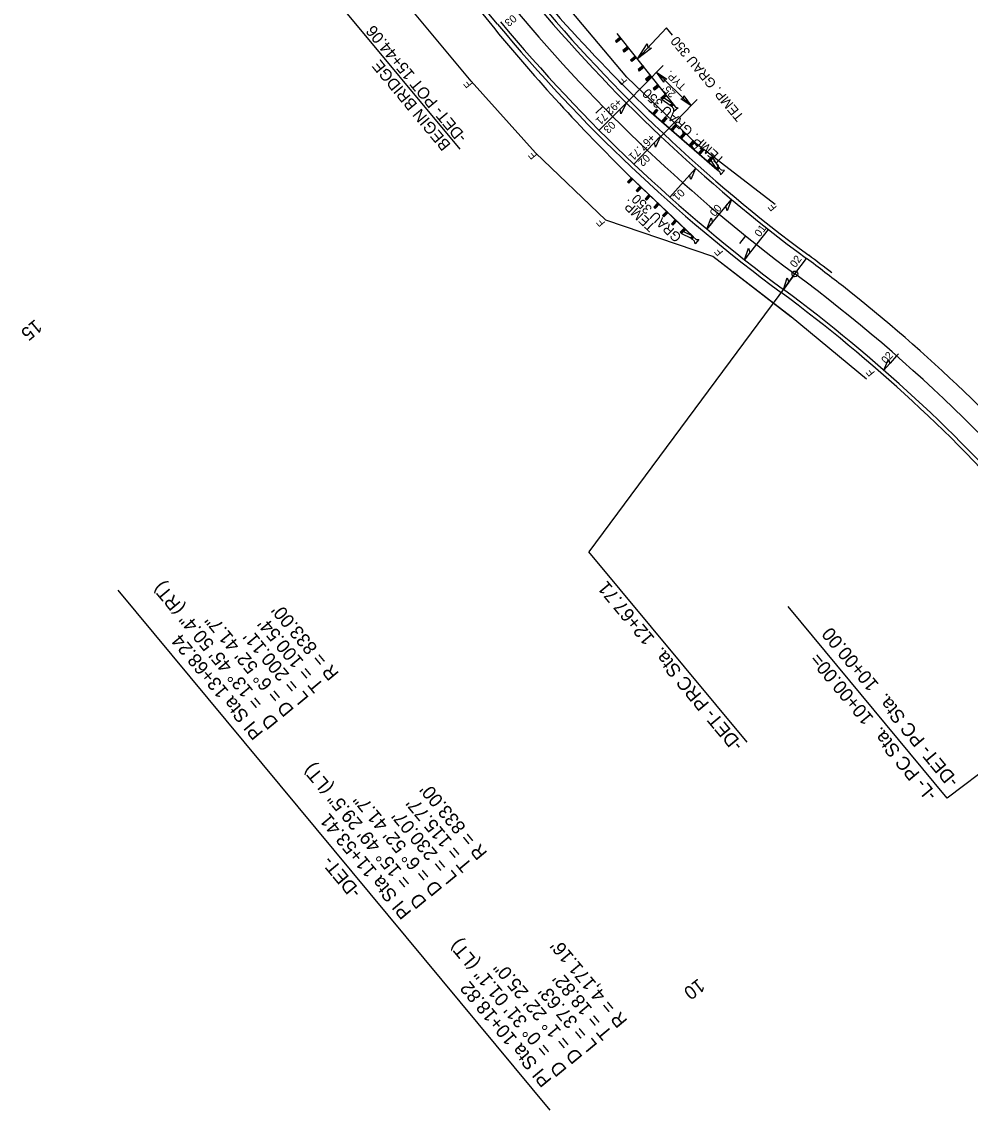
# Model space of a CAD drawing. Extents: x 2597390 to 2598563, y 852595 to 853909.
# Drawn here: x 2597806 to 2598297, y 852595 to 853159 of the extents above; entities that cross this region are included whole.
import ezdxf

# ---------------------------------------------------------------- set-up
doc = ezdxf.new("R2010")
doc.units = 0
for name, color, linetype in [('Prop DSN Text', 7, 'Continuous'), ('Prop EOT', 7, 'Continuous'), ('Prop Guardrail Anchor Unit CELL', 7, 'Continuous'), ('Prop Guardrail Temporary', 7, 'Continuous'), ('Prop Horizontal Alignment', 7, 'Continuous'), ('Prop Horizontal Alignment Curve and Spiral Data', 7, 'Continuous'), ('Prop Horizontal Alignment Station Label', 7, 'Continuous'), ('Prop Horizontal Alignment Tick Label', 7, 'Continuous'), ('Prop Horizontal Alignment Tick Small', 7, 'Continuous'), ('Prop Lane Lines', 7, 'Continuous'), ('Prop Paved Shoulder', 7, 'Continuous'), ('Prop SS Fill Line', 7, 'Continuous'), ('Prop SS Misc', 7, 'Continuous'), ('Prop Superelevation  Arrow CELL', 7, 'Continuous'), ('Prop Superelevation Label', 7, 'Continuous'), ('Prop Terminator CELL', 7, 'Continuous')]:
    doc.layers.add(name, color=color, linetype=linetype)

msp = doc.modelspace()

# ---------------------------------------------------------------- linework, layer by layer
at = {"layer": 'Prop DSN Text'}
msp.add_lwpolyline([(2598032.88, 853093.04), (2597970.16, 853168.56), (2598012.79, 853224.24)], dxfattribs=at)
at = {"layer": 'Prop EOT'}
for centre, radius, start, end in [((2598702.35, 853697.75), 823, 219.70669, 233.47068), ((2598702.35, 853697.75), 843, 219.70669, 233.47068), ((2597710.69, 852359.03), 843, 51.83177, 53.47068), ((2597710.69, 852359.03), 823, 41.12046, 53.47068)]:
    msp.add_arc(centre, radius, start, end, dxfattribs=at)
at = {"layer": 'Prop Guardrail Anchor Unit CELL'}
for p, q in [((2598115.79, 853151.04), (2598113.44, 853149.17)), ((2598115.24, 853149.33), (2598113.44, 853149.17)), ((2598113.44, 853149.17), (2598114.07, 853148.39)), ((2598116.41, 853150.26), (2598114.07, 853148.39)), ((2598114.07, 853148.39), (2598114.61, 853150.11)), ((2598114.2, 853153.03), (2598143.35, 853116.48)), ((2598114.61, 853150.11), (2598116.41, 853150.26)), ((2598114.61, 853150.11), (2598115.24, 853149.33)), ((2598115.24, 853149.33), (2598115.79, 853151.04)), ((2598116.41, 853150.26), (2598115.24, 853149.33)), ((2598115.79, 853151.04), (2598116.41, 853150.26)), ((2598119.72, 853146.12), (2598117.33, 853144.21)), ((2598119.15, 853144.38), (2598117.33, 853144.21)), ((2598117.33, 853144.21), (2598117.95, 853143.43)), ((2598120.34, 853145.33), (2598117.95, 853143.43)), ((2598117.95, 853143.43), (2598118.52, 853145.16)), ((2598118.52, 853145.16), (2598120.34, 853145.33)), ((2598118.52, 853145.16), (2598119.15, 853144.38)), ((2598119.72, 853146.12), (2598119.15, 853144.38)), ((2598123.64, 853141.19), (2598121.26, 853139.29)), ((2598123.08, 853139.46), (2598121.26, 853139.29)), ((2598121.26, 853139.29), (2598121.89, 853138.51)), ((2598124.27, 853140.41), (2598121.89, 853138.51)), ((2598121.89, 853138.51), (2598122.45, 853140.24)), ((2598122.45, 853140.24), (2598124.27, 853140.41)), ((2598122.45, 853140.24), (2598123.08, 853139.46)), ((2598123.64, 853141.19), (2598123.08, 853139.46)), ((2598127.57, 853136.26), (2598125.2, 853134.37)), ((2598127.01, 853134.53), (2598125.2, 853134.37)), ((2598125.2, 853134.37), (2598125.82, 853133.59)), ((2598128.2, 853135.48), (2598125.82, 853133.59)), ((2598125.82, 853133.59), (2598126.39, 853135.32)), ((2598126.39, 853135.32), (2598128.2, 853135.48)), ((2598126.39, 853135.32), (2598127.01, 853134.53)), ((2598127.57, 853136.26), (2598127.01, 853134.53)), ((2598127.57, 853136.26), (2598128.2, 853135.48)), ((2598131.5, 853131.34), (2598129.05, 853129.38)), ((2598130.9, 853129.58), (2598129.05, 853129.38)), ((2598129.05, 853129.38), (2598129.67, 853128.6)), ((2598132.13, 853130.55), (2598129.67, 853128.6)), ((2598129.67, 853128.6), (2598130.27, 853130.36)), ((2598130.27, 853130.36), (2598132.13, 853130.55)), ((2598130.27, 853130.36), (2598130.9, 853129.58)), ((2598131.5, 853131.34), (2598130.9, 853129.58)), ((2598135.43, 853126.41), (2598133.08, 853124.54)), ((2598135.43, 853126.41), (2598134.88, 853124.69)), ((2598134.88, 853124.69), (2598133.08, 853124.54)), ((2598133.08, 853124.54), (2598133.71, 853123.76)), ((2598136.05, 853125.63), (2598133.71, 853123.76)), ((2598133.71, 853123.76), (2598134.26, 853125.47)), ((2598134.26, 853125.47), (2598136.05, 853125.63)), ((2598134.26, 853125.47), (2598134.88, 853124.69)), ((2598139.36, 853121.48), (2598136.96, 853119.57)), ((2598139.98, 853120.7), (2598137.59, 853118.79)), ((2598137.59, 853118.79), (2598138.16, 853120.53)), ((2598138.16, 853120.53), (2598139.98, 853120.7)), ((2598138.16, 853120.53), (2598138.78, 853119.74)), ((2598139.36, 853121.48), (2598138.78, 853119.74)), ((2598138.78, 853119.74), (2598136.96, 853119.57)), ((2598136.96, 853119.57), (2598137.59, 853118.79)), ((2598137.59, 853118.79), (2598141.86, 853115.93)), ((2598138.78, 853119.74), (2598143.04, 853116.87)), ((2598143.04, 853116.87), (2598141.86, 853115.93)), ((2598143.66, 853116.09), (2598141.86, 853115.93)), ((2598141.86, 853115.93), (2598142.18, 853115.54)), ((2598141.86, 853115.93), (2598142.49, 853115.15)), ((2598142.37, 853115.63), (2598142.84, 853116.02)), ((2598143.67, 853114.05), (2598142.37, 853115.63)), ((2598142.49, 853115.15), (2598143.04, 853116.87)), ((2598143.66, 853116.09), (2598142.49, 853115.15)), ((2598142.84, 853116.02), (2598143.31, 853116.4)), ((2598143.31, 853116.4), (2598144.62, 853114.83)), ((2598130.77, 853113.24), (2598166.06, 853082.58)), ((2598132.69, 853111.57), (2598134.66, 853113.84)), ((2598134.43, 853112.05), (2598132.69, 853111.57)), ((2598132.69, 853111.57), (2598133.44, 853110.92)), ((2598133.44, 853110.92), (2598135.41, 853113.18)), ((2598133.67, 853112.7), (2598133.44, 853110.92)), ((2598133.44, 853110.92), (2598134.43, 853112.05)), ((2598135.41, 853113.18), (2598133.67, 853112.7)), ((2598133.67, 853112.7), (2598134.43, 853112.05)), ((2598134.43, 853112.05), (2598134.66, 853113.84)), ((2598134.66, 853113.84), (2598135.41, 853113.18)), ((2598137.45, 853107.44), (2598139.45, 853109.74)), ((2598139.2, 853107.94), (2598139.45, 853109.74)), ((2598139.45, 853109.74), (2598140.2, 853109.09)), ((2598143.76, 853112.6), (2598143.67, 853114.05)), ((2598146.03, 853114.47), (2598143.76, 853112.6)), ((2598144.62, 853114.83), (2598146.03, 853114.47)), ((2598137.45, 853107.44), (2598139.2, 853107.94)), ((2598138.2, 853106.78), (2598140.2, 853109.09)), ((2598138.45, 853108.59), (2598138.2, 853106.78)), ((2598140.2, 853109.09), (2598138.45, 853108.59)), ((2598138.45, 853108.59), (2598139.2, 853107.94)), ((2598142.2, 853103.31), (2598144.2, 853105.61)), ((2598142.2, 853103.31), (2598143.96, 853103.8)), ((2598142.96, 853102.65), (2598144.96, 853104.95)), ((2598143.2, 853104.46), (2598142.96, 853102.65)), ((2598144.96, 853104.95), (2598143.2, 853104.46)), ((2598143.2, 853104.46), (2598143.96, 853103.8)), ((2598143.96, 853103.8), (2598144.2, 853105.61)), ((2598144.2, 853105.61), (2598144.96, 853104.95)), ((2598146.96, 853099.17), (2598148.95, 853101.47)), ((2598146.96, 853099.17), (2598148.71, 853099.67)), ((2598146.96, 853099.17), (2598147.71, 853098.52)), ((2598147.71, 853098.52), (2598149.71, 853100.81)), ((2598147.96, 853100.32), (2598147.71, 853098.52)), ((2598149.71, 853100.81), (2598147.96, 853100.32)), ((2598147.96, 853100.32), (2598148.71, 853099.67)), ((2598148.71, 853099.67), (2598148.95, 853101.47)), ((2598148.95, 853101.47), (2598149.71, 853100.81)), ((2598151.72, 853095.04), (2598153.77, 853097.41)), ((2598151.72, 853095.04), (2598153.5, 853095.57)), ((2598152.47, 853094.39), (2598154.53, 853096.76)), ((2598152.74, 853096.23), (2598152.47, 853094.39)), ((2598154.53, 853096.76), (2598152.74, 853096.23)), ((2598152.74, 853096.23), (2598153.5, 853095.57)), ((2598153.5, 853095.57), (2598153.77, 853097.41)), ((2598153.77, 853097.41), (2598154.53, 853096.76)), ((2598156.47, 853090.91), (2598158.44, 853093.17)), ((2598157.23, 853090.25), (2598159.2, 853092.52)), ((2598159.2, 853092.52), (2598157.46, 853092.04)), ((2598158.21, 853091.39), (2598158.44, 853093.17)), ((2598158.44, 853093.17), (2598159.2, 853092.52)), ((2598156.47, 853090.91), (2598158.21, 853091.39)), ((2598157.46, 853092.04), (2598157.23, 853090.25)), ((2598157.46, 853092.04), (2598158.21, 853091.39)), ((2598161.23, 853086.78), (2598163.24, 853089.09)), ((2598161.23, 853086.78), (2598162.99, 853087.28)), ((2598161.99, 853086.12), (2598164, 853088.43)), ((2598162.24, 853087.93), (2598161.99, 853086.12)), ((2598164, 853088.43), (2598162.24, 853087.93)), ((2598162.24, 853087.93), (2598162.99, 853087.28)), ((2598162.99, 853087.28), (2598163.24, 853089.09)), ((2598162.99, 853087.28), (2598165.69, 853082.91)), ((2598163.24, 853089.09), (2598164, 853088.43)), ((2598164, 853088.43), (2598166.67, 853084.04)), ((2598165.69, 853082.91), (2598166.67, 853084.04)), ((2598167.42, 853083.38), (2598165.69, 853082.91)), ((2598166.55, 853083.07), (2598166.14, 853082.62)), ((2598166.14, 853082.62), (2598167.66, 853081.25)), ((2598166.44, 853082.25), (2598166.67, 853084.04)), ((2598166.44, 853082.25), (2598167.42, 853083.38)), ((2598166.95, 853083.52), (2598166.55, 853083.07)), ((2598166.67, 853084.04), (2598167.05, 853083.71)), ((2598166.67, 853084.04), (2598167.42, 853083.38)), ((2598168.47, 853082.15), (2598166.95, 853083.52)), ((2598167.66, 853081.25), (2598167.95, 853079.82)), ((2598167.95, 853079.82), (2598169.92, 853082)), ((2598169.92, 853082), (2598168.47, 853082.15)), ((2598121.77, 853078.27), (2598119.7, 853076.1)), ((2598121.46, 853076.5), (2598119.7, 853076.1)), ((2598119.7, 853076.1), (2598120.43, 853075.41)), ((2598119.93, 853080.03), (2598153.78, 853047.78)), ((2598122.5, 853077.58), (2598120.43, 853075.41)), ((2598120.43, 853075.41), (2598120.74, 853077.19)), ((2598120.74, 853077.19), (2598122.5, 853077.58)), ((2598120.74, 853077.19), (2598121.46, 853076.5)), ((2598121.46, 853076.5), (2598121.77, 853078.27)), ((2598122.5, 853077.58), (2598121.46, 853076.5)), ((2598121.77, 853078.27), (2598122.5, 853077.58)), ((2598126.33, 853073.93), (2598124.23, 853071.72)), ((2598126.01, 853072.13), (2598124.23, 853071.72)), ((2598124.23, 853071.72), (2598124.95, 853071.03)), ((2598127.06, 853073.24), (2598124.95, 853071.03)), ((2598124.95, 853071.03), (2598125.28, 853072.82)), ((2598125.28, 853072.82), (2598127.06, 853073.24)), ((2598125.28, 853072.82), (2598126.01, 853072.13)), ((2598126.33, 853073.93), (2598126.01, 853072.13)), ((2598130.9, 853069.58), (2598128.79, 853067.37)), ((2598130.57, 853067.79), (2598128.79, 853067.37)), ((2598128.79, 853067.37), (2598129.52, 853066.68)), ((2598131.62, 853068.89), (2598129.52, 853066.68)), ((2598129.52, 853066.68), (2598129.85, 853068.48)), ((2598129.85, 853068.48), (2598131.62, 853068.89)), ((2598129.85, 853068.48), (2598130.57, 853067.79)), ((2598130.9, 853069.58), (2598130.57, 853067.79)), ((2598135.46, 853065.23), (2598133.37, 853063.03)), ((2598136.18, 853064.54), (2598134.09, 853062.35)), ((2598134.09, 853062.35), (2598134.41, 853064.13)), ((2598134.41, 853064.13), (2598136.18, 853064.54)), ((2598134.41, 853064.13), (2598135.14, 853063.44)), ((2598135.46, 853065.23), (2598135.14, 853063.44)), ((2598135.46, 853065.23), (2598136.18, 853064.54)), ((2598135.14, 853063.44), (2598133.37, 853063.03)), ((2598133.37, 853063.03), (2598134.09, 853062.35)), ((2598140.02, 853060.89), (2598137.86, 853058.61)), ((2598139.66, 853059.06), (2598137.86, 853058.61)), ((2598137.86, 853058.61), (2598138.58, 853057.92)), ((2598140.75, 853060.2), (2598138.58, 853057.92)), ((2598138.58, 853057.92), (2598138.94, 853059.75)), ((2598138.94, 853059.75), (2598140.75, 853060.2)), ((2598138.94, 853059.75), (2598139.66, 853059.06)), ((2598140.02, 853060.89), (2598139.66, 853059.06)), ((2598144.58, 853056.54), (2598142.51, 853054.37)), ((2598144.27, 853054.76), (2598142.51, 853054.37)), ((2598142.51, 853054.37), (2598143.24, 853053.68)), ((2598145.31, 853055.85), (2598143.24, 853053.68)), ((2598143.24, 853053.68), (2598143.55, 853055.45)), ((2598143.55, 853055.45), (2598145.31, 853055.85)), ((2598143.55, 853055.45), (2598144.27, 853054.76)), ((2598144.58, 853056.54), (2598144.27, 853054.76)), ((2598149.15, 853052.19), (2598147.03, 853049.97)), ((2598148.81, 853050.39), (2598147.03, 853049.97)), ((2598147.03, 853049.97), (2598147.76, 853049.28)), ((2598149.87, 853051.5), (2598147.76, 853049.28)), ((2598147.76, 853049.28), (2598148.09, 853051.08)), ((2598147.76, 853049.28), (2598152.38, 853047.04)), ((2598148.09, 853051.08), (2598149.87, 853051.5)), ((2598148.09, 853051.08), (2598148.81, 853050.39)), ((2598149.15, 853052.19), (2598148.81, 853050.39)), ((2598148.81, 853050.39), (2598153.42, 853048.12)), ((2598153.42, 853048.12), (2598152.38, 853047.04)), ((2598154.14, 853047.43), (2598152.38, 853047.04)), ((2598152.92, 853046.8), (2598153.34, 853047.25)), ((2598153.11, 853046.35), (2598153.42, 853048.12)), ((2598154.14, 853047.43), (2598153.11, 853046.35)), ((2598153.34, 853047.25), (2598153.75, 853047.7)), ((2598153.75, 853047.7), (2598155.26, 853046.32)), ((2598152.38, 853047.04), (2598152.75, 853046.69)), ((2598152.38, 853047.04), (2598153.11, 853046.35)), ((2598154.43, 853045.42), (2598152.92, 853046.8)), ((2598154.72, 853043.99), (2598154.43, 853045.42)), ((2598156.71, 853046.15), (2598154.72, 853043.99)), ((2598155.26, 853046.32), (2598156.71, 853046.15))]:
    msp.add_line(p, q, dxfattribs=at)
at = {"layer": 'Prop Guardrail Temporary'}
for p, q in [((2598014, 853200.87), (2598050.83, 853155.47)), ((2598167.66, 853081.25), (2598130.77, 853113.24)), ((2598153.75, 853047.7), (2598119.93, 853080.03))]:
    msp.add_line(p, q, dxfattribs=at)
for centre, radius, start, end in [((2598696.5, 853703.86), 817.85, 221.28346, 226.23325), ((2598771.67, 853746.31), 932.04, 219.34005, 225.63259)]:
    msp.add_arc(centre, radius, start, end, dxfattribs=at)
at = {"layer": 'Prop Horizontal Alignment'}
for centre, start, end in [((2598702.35, 853697.75), 219.70669, 233.47068), ((2597710.69, 852359.03), 37.64582, 53.47068)]:
    msp.add_arc(centre, 833, start, end, dxfattribs=at)
at = {"layer": 'Prop Horizontal Alignment Station Label'}
for p, q in [((2598205.63, 853027.18), (2598099.7, 852884.18)), ((2598181.69, 852785.43), (2598099.7, 852884.18)), ((2598079.66, 852594.52), (2597855.6, 852864.33)), ((2598285.55, 852756.47), (2598202.99, 852855.89)), ((2598393.11, 852837.9), (2598285.55, 852756.47))]:
    msp.add_line(p, q, dxfattribs=at)
msp.add_circle((2598206.52, 853028.39), 1.5, dxfattribs=at)
at = {"layer": 'Prop Horizontal Alignment Tick Small'}
for p, q in [((2598106.9, 853115.23), (2598103.33, 853111.73)), ((2598180.95, 853048.11), (2598177.82, 853044.21)), ((2598259.23, 852985.92), (2598255.94, 852982.16))]:
    msp.add_line(p, q, dxfattribs=at)
at = {"layer": 'Prop Lane Lines'}
msp.add_arc((2597710.69, 852359.03), 843, 40.54315, 51.83177, dxfattribs=at)
at = {"layer": 'Prop Paved Shoulder'}
msp.add_line((2598052.27, 853157.91), (2598003.56, 853216.57), dxfattribs=at)
for centre, radius, start, end in [((2598702.35, 853697.75), 821, 219.70669, 233.47068), ((2598702.35, 853697.75), 845, 219.70669, 233.47068), ((2597710.69, 852359.03), 845, 52.44833, 53.47068), ((2597710.69, 852359.03), 821, 41.12046, 53.47068)]:
    msp.add_arc(centre, radius, start, end, dxfattribs=at)
at = {"layer": 'Prop SS Fill Line'}
for p, q in [((2598038.59, 853128.35), (2598006.57, 853166.75)), ((2598119.31, 853130.39), (2598087.2, 853168.72)), ((2598072.04, 853091.13), (2598038.59, 853128.35)), ((2598155.73, 853095.64), (2598119.31, 853130.39)), ((2598196.3, 853064.34), (2598155.73, 853095.64)), ((2598108.37, 853056.32), (2598072.04, 853091.13)), ((2598163.92, 853037.45), (2598108.37, 853056.32)), ((2598204.49, 853006.15), (2598163.92, 853037.45)), ((2598204.5, 853006.15), (2598163.92, 853037.45)), ((2598243.69, 852973.71), (2598204.5, 853006.15))]:
    msp.add_line(p, q, dxfattribs=at)
at = {"layer": 'Prop Superelevation  Arrow CELL'}
for points in [[(2598119.11, 853117.09), (2598116.27, 853111.44), (2598115.83, 853113.83)], [(2598136.8, 853099.85), (2598134.13, 853094.12), (2598133.62, 853096.49)], [(2598154.99, 853083.15), (2598152.5, 853077.34), (2598151.92, 853079.69)], [(2598173.68, 853067), (2598171.36, 853061.12), (2598170.71, 853063.46)], [(2598160.83, 853051.68), (2598163.15, 853057.56), (2598163.8, 853055.22)], [(2598180.46, 853035.72), (2598182.43, 853041.73), (2598183.22, 853039.43)], [(2598200.57, 853020.35), (2598202.53, 853026.36), (2598203.32, 853024.07)], [(2598252.64, 852978.4), (2598255.09, 852984.23), (2598255.69, 852981.88)]]:
    msp.add_lwpolyline(points, close=True, dxfattribs=at)
at = {"layer": 'Prop Superelevation Label'}
for p, q in [((2598119.14, 853117.06), (2598138.21, 853136.55)), ((2598152.67, 853115.57), (2598134.8, 853133.06)), ((2598104.94, 853102.98), (2598119.11, 853117.09)), ((2598137.04, 853099.62), (2598155.89, 853118.86)), ((2598136.8, 853099.85), (2598123.05, 853085.32)), ((2598141.69, 853068.22), (2598154.99, 853083.15)), ((2598160.83, 853051.68), (2598173.68, 853067)), ((2598180.46, 853035.72), (2598192.85, 853051.42)), ((2598206.52, 853028.39), (2598212.47, 853036.42)), ((2598200.57, 853020.35), (2598206.52, 853028.39)), ((2598260.17, 852987), (2598252.64, 852978.4))]:
    msp.add_line(p, q, dxfattribs=at)
msp.add_lwpolyline([(2598142.95, 853152.3), (2598139.87, 853156), (2598124.7, 853139.87)], dxfattribs=at)
at = {"layer": 'Prop Terminator CELL'}
for points in [[(2598132.1, 853145.51), (2598124.81, 853140.02), (2598129.84, 853147.7), (2598130.22, 853145.77)], [(2598138.55, 853127.88), (2598134.8, 853133.06), (2598140.11, 853129.43), (2598138.76, 853129.19)], [(2598148.93, 853120.76), (2598152.67, 853115.57), (2598147.36, 853119.2), (2598148.72, 853119.44)]]:
    msp.add_lwpolyline(points, close=True, dxfattribs=at)

# ---------------------------------------------------------------- texts
at = {"layer": 'Prop DSN Text'}
for s, p in [('-DET- POT 15+44.06', (2598036.71, 853099.46)), (' BEGIN BRIDGE', (2598029.79, 853093.71))]:
    msp.add_text(s, height=6, rotation=129.7066, dxfattribs=at).set_placement(p)
at = {"layer": 'Prop Guardrail Anchor Unit CELL'}
for s, rotation, p in [('TEMP. GRAU 350', 129.7067, (2598180.38, 853110.12)), ('TEMP. GRAU 350', 137.1968, (2598170.36, 853087.91)), ('TEMP.', 136.286, (2598134.56, 853053.4)), ('GRAU 350', 136.286, (2598148.13, 853047.88))]:
    msp.add_text(s, height=5, rotation=rotation, dxfattribs=at).set_placement(p)
at = {"layer": 'Prop Horizontal Alignment Curve and Spiral Data'}
for s, p in [('= 13%%d 45\' 50.4" (RT)', (2597931.07, 852805.97)), ("R = 833.00'", (2597970.36, 852821.13)), ('D = 6%%d 52\' 41.7"', (2597947.06, 852802.35)), ("T = 100.54'", (2597962.55, 852814.84)), ('PI Sta 13+68.24', (2597931.08, 852790.33)), ("L = 200.11'", (2597954.73, 852808.53)), ('D', (2597938.92, 852795.78)), ('= 15%%d 49\' 29.5" (LT)', (2598008.03, 852712.89)), ("R = 833.00'", (2598047.33, 852728.07)), ('D = 6%%d 52\' 41.7"', (2598024.03, 852709.29)), ("T = 115.77'", (2598039.5, 852721.75)), ('PI Sta 11+53.41', (2598008.01, 852697.24)), ("L = 230.07'", (2598031.74, 852715.5)), ('-DET-', (2597981.97, 852707.87)), ('D', (2598015.89, 852702.72)), ('= 0%%d 31\' 01.1" (LT)', (2598080.68, 852625.77)), ("R = 4,171.16'", (2598120.02, 852640.98)), ('D = 1%%d 22\' 25.0"', (2598096.76, 852622.23)), ("T = 18.82'", (2598112.2, 852634.68)), ('PI Sta 10+18.82', (2598080.74, 852610.18)), ("L = 37.63'", (2598104.42, 852628.4)), ('D', (2598088.6, 852615.65))]:
    msp.add_text(s, height=7, rotation=129.7067, dxfattribs=at).set_placement(p)
at = {"layer": 'Prop Horizontal Alignment Station Label'}
for s, p in [('-DET- PRC Sta.  12+67.71', (2598180.02, 852784.19)), ('-DET- PC Sta.  10+00.00', (2598291.91, 852765.48)), ('-L- PC Sta.  10+00.00=', (2598280.62, 852758.38))]:
    msp.add_text(s, height=7, rotation=129.7067, dxfattribs=at).set_placement(p)
at = {"layer": 'Prop Horizontal Alignment Tick Label'}
for s, rotation, p in [('15', 219.7067, (2597812.48, 853005.17)), ('10', 217.1289, (2598156.49, 852663.15))]:
    msp.add_text(s, height=7, rotation=rotation, dxfattribs=at).set_placement(p)
at = {"layer": 'Prop SS Misc'}
for p in [(2598039.49, 853126.87), (2598119.83, 853128.57), (2598157.73, 853095.05), (2598073.05, 853089.87), (2598197.4, 853063), (2598108.39, 853054.95), (2598169.59, 853039.75), (2598248.24, 852977.28)]:
    msp.add_text('F', height=4, rotation=129.7067, dxfattribs=at).set_placement(p)
at = {"layer": 'Prop Superelevation Label'}
for s, rotation, p in [('03', 219.7067, (2598060.12, 853163.2)), ('TYP.', 135.6099, (2598150.45, 853125.93)), ("25'", 136.6099, (2598145.03, 853122.24)), ('+92.71', 224.8726, (2598114.49, 853119.76)), ('03', 224.8726, (2598111.14, 853107.94)), ('+67.71', 224.8726, (2598131.63, 853101.28)), ('02', 224.8726, (2598129.02, 853090.8)), ('01', 224.8726, (2598146.97, 853072.83)), ('00', 50.0313, (2598165.06, 853057.79)), ('01', 53.4707, (2598188.37, 853047.23)), ('02', 53.4707, (2598206.76, 853031.34)), ('02', 48.8137, (2598253.88, 852981.45))]:
    msp.add_text(s, height=4, rotation=rotation, dxfattribs=at).set_placement(p)

doc.saveas('drawing.dxf')
